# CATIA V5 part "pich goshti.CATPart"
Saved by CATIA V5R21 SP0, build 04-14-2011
Part number: Part1
Bounding box of the stored display mesh (mm): x -20 to 20, y -180 to 200, z -20 to 20
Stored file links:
  C:\Users\amir\Desktop\pich goshti.CATPart
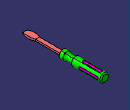
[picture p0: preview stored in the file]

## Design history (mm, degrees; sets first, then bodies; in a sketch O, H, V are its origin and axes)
Body1 (main body)
  Sketch1 on yz-plane, origin (0, 0, 0), H (0, 1, 0), V (0, 0, 1)
    line L1 (0, 0) -> (200, 0)
    line L2 (200, 0) -> (200, 20)
    line L3 (200, 20) -> (60, 20)
    arc A1 centre (40, 42.3607) radius 30 from (60, 20) to (20, 20) cw
    point P4 (40, 42.3607)
    point P5 (20, 20)
    line L4 (20, 20) -> (0, 20)
    point P6 (0, 20)
    line L5 (0, 20) -> (0, 0)
    distance P5 L5 = 20
    distance P4 L5 = 40
    distance L2 L5 = 200
    radius A1 = 30
    length L2 = 20
    horizontal: L1 H, L3 H, L4 H
    vertical: L2 V, L5 V
    coincidence: P5 L3, P6 V
  Shaft1: profile Sketch1, axis Sketch1.L1, angle 360
  Sketch2 on face of Shaft1 from Sketch1.L5, origin (0, 0, 0), H (1, 0, 0), V (0, 0, 1)
    line L1 (9, 4) -> (9, -4)
    line L2 (9, -4) -> (-9, -4)
    line L3 (-9, -4) -> (-9, 4)
    line L4 (-9, 4) -> (9, 4)
    length L4 = 18
    length L3 = 8
    vertical: L1 V, L3 V
    horizontal: L2 H, L4 H
    equidistance: L1 L3 O, L2 L4 O
  Pad1: profile Sketch2, direction (0, -1, 0), length 120
  Plane1: type Offset, RefPlane end face of Pad1, Offset 30, reversed
  Sketch3 on Plane1, origin (0, -150, 0), H (-1, 0, 0), V (0, 0, 1)
    line L1 (15, 5) -> (15, -5)
    line L2 (15, -5) -> (-15, -5)
    line L3 (-15, -5) -> (-15, 5)
    line L4 (-15, 5) -> (15, 5)
    length L4 = 30
    length L1 = 10
    vertical: L1 V, L3 V
    horizontal: L2 H, L4 H
    equidistance: L1 L3 O, L2 L4 O
  Plane2: type Offset, RefPlane Plane1, Offset 30, reversed
  Sketch4 on Plane2, origin (0, -180, 0), H (-1, 0, 0), V (0, 0, 1)
    line L1 (10, 2) -> (10, -2)
    line L2 (10, -2) -> (-10, -2)
    line L3 (-10, -2) -> (-10, 2)
    line L4 (-10, 2) -> (10, 2)
    length L4 = 20
    length L3 = 4
    vertical: L1 V, L3 V
    horizontal: L2 H, L4 H
    equidistance: L1 L3 O, L2 L4 O
  Plane3: type Offset, RefPlane end face of Pad1, Offset 0, reversed
  Sketch5 on Plane3, origin (0, -120, 0), H (-1, 0, 0), V (0, 0, 1)
    line L1 (9, 4) -> (9, -4)
    line L2 (9, -4) -> (-9, -4)
    line L3 (-9, -4) -> (-9, 4)
    line L4 (-9, 4) -> (9, 4)
    length L1 = 8
    length L4 = 18
    vertical: L1 V, L3 V
    horizontal: L2 H, L4 H
    equidistance: L1 L3 O, L2 L4 O
  Loft1: solid, Sections (Sketch5; Sketch3; Sketch4)
  Fillet1: radius 5, on edge [face of Shaft1 from Sketch1.L3 | face of Shaft1 from Sketch1.L2]
  Fillet2: radius 4, on edge [face of Shaft1 from Sketch1.L5 | face of Pad1 from Sketch2.L4]
  Fillet3: radius 4, on edge [face of Shaft1 from Sketch1.L5 | face of Pad1 from Sketch2.L2]
  Fillet4: radius 2, on edge [face of Shaft1 from Sketch1.L5 | face of Shaft1 from Sketch1.L4]
  Fillet5: radius 2, on edge [face of Shaft1 from Sketch1.L4 | face of Shaft1 from Sketch1.A1]
  Fillet6: radius 2, on edge [face of Shaft1 from Sketch1.A1 | face of Shaft1 from Sketch1.L3]
  Plane4: type Offset, RefPlane xy-plane, Offset 20
  Sketch6 on Plane4, origin (0, 0, 20), H (1, 0, 0), V (0, 1, 0)
    point P1 (0, 140)
    line L1 (6, 185) -> (6, 95)
    line L2 (6, 95) -> (-6, 95)
    line L3 (-6, 95) -> (-6, 185)
    line L4 (-6, 185) -> (6, 185)
    length L4 = 12
    distance P1 H = 140
    distance L2 H = 95
    coincidence: P1 V
    vertical: L1 V, L3 V
    horizontal: L2 H, L4 H
    equidistance: L1 L3 P1, L2 L4 P1
  Pocket1: profile Sketch6, direction (0, 0, -1), length 3
  Fillet7: radius 2, on edge [face of Pocket1 from Sketch6.L2 | face of Pocket1 from Sketch6.L3]; edge [face of Pocket1 from Sketch6.L1 | face of Pocket1 from Sketch6.L2]; edge [face of Pocket1 from Sketch6.L4 | face of Pocket1 from Sketch6.L1]; edge [face of Pocket1 from Sketch6.L3 | face of Pocket1 from Sketch6.L4]
  Fillet8: radius 0.5, on edge [face of Pocket1 from Sketch6.L3 | face of Shaft1 from Sketch1.L3]
  Fillet9: radius 0.5, on edge [face of Pocket1 from Sketch6.L3 | end face of Pocket1]
  Sketch7 on yz-plane, origin (0, 0, 0), H (0, 1, 0), V (0, 0, 1)
    line L1 (0, 0) -> (214.2038, 0)
    horizontal: L1 H
  CircPattern1: of Pocket1, Fillet7, Fillet8, Fillet9, instances 4, angular step 90, axis from Sketch7.L1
